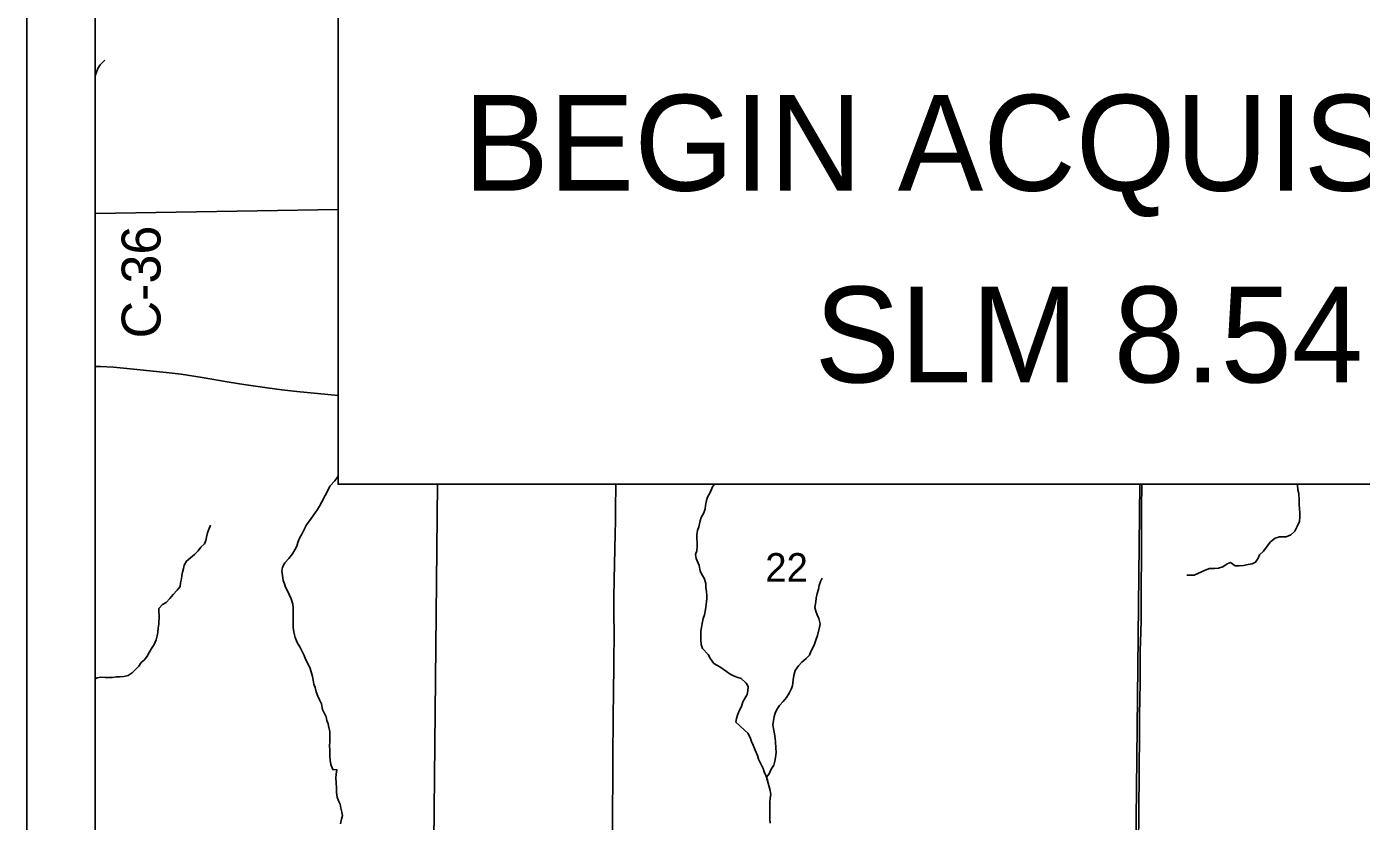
# Model space of a CAD drawing. Extents: x 0 to 34, y 0 to 22.
# Drawn here: x 2 to 3.95, y 18.022 to 19.182 of the extents above; entities that cross this region are included whole.
import ezdxf

# ---------------------------------------------------------------- set-up
doc = ezdxf.new("R2010")
doc.units = 0
for name, color, linetype in [('Default', 7, 'Continuous'), ('GM_X_County_Road', 7, 'Continuous'), ('GM_X_County_Road_Text', 7, 'Continuous'), ('GM_X_Minor_River', 7, 'Continuous'), ('GM_X_Section', 7, 'Continuous'), ('GM_X_Section_Text', 7, 'Continuous'), ('GM_X_State_Route', 7, 'Continuous'), ('GM_X_Township_Road', 7, 'Continuous'), ('SH_Data', 7, 'Continuous'), ('SH_Text', 7, 'Continuous')]:
    doc.layers.add(name, color=color, linetype=linetype)

msp = doc.modelspace()

# ---------------------------------------------------------------- linework, layer by layer
at = {"layer": 'Default'}
for points in [[(2.6062, 19.2311), (2.6102, 19.9231), (2.1, 19.9187), (2.1, 18.9091), (2.4548, 18.9153), (2.4548, 19.2311)], [(2.4548, 18.9153), (2.1, 18.9091), (2.1, 17.8937), (2.5938, 17.8965), (2.6002, 18.514), (2.4548, 18.514)]]:
    msp.add_lwpolyline(points, close=True, dxfattribs=at)
at = {"layer": 'GM_X_County_Road'}
msp.add_lwpolyline([(2.855, 17.896), (2.8551, 17.9234), (2.8554, 17.9703), (2.8559, 18.0107), (2.8562, 18.1102), (2.8563, 18.1288), (2.8567, 18.1597), (2.8569, 18.1752), (2.8573, 18.2095), (2.8578, 18.2498), (2.8579, 18.2683), (2.8581, 18.2828), (2.8581, 18.3026), (2.8579, 18.3181), (2.8579, 18.3492), (2.8581, 18.3742), (2.8598, 18.4422), (2.8601, 18.4603), (2.8603, 18.4764), (2.8608, 18.514)], dxfattribs=at)
at = {"layer": 'GM_X_Minor_River'}
for points in [[(2.1, 19.1106), (2.1018, 19.1159), (2.104, 19.1209), (2.1074, 19.1266), (2.1142, 19.1331)], [(2.4586, 18.0183), (2.4601, 18.0248), (2.4612, 18.0301), (2.4604, 18.0351), (2.4589, 18.0408), (2.4577, 18.0469), (2.4554, 18.0518), (2.4535, 18.0571), (2.4527, 18.0639), (2.4526, 18.07), (2.4522, 18.0784), (2.4518, 18.0849), (2.4522, 18.0906), (2.4529, 18.097), (2.4472, 18.0974), (2.4441, 18.1046), (2.4433, 18.111), (2.4429, 18.1167), (2.4429, 18.1263), (2.4424, 18.132), (2.4428, 18.138), (2.4427, 18.1529), (2.4415, 18.1589), (2.4404, 18.1639), (2.4385, 18.1692), (2.4373, 18.1745), (2.4323, 18.1851), (2.4307, 18.1931), (2.4277, 18.1992), (2.4254, 18.2045), (2.4231, 18.2106), (2.4215, 18.217), (2.4196, 18.222), (2.4184, 18.228), (2.4176, 18.2334), (2.4157, 18.2402), (2.4134, 18.2463), (2.4072, 18.2584), (2.4053, 18.2637), (2.4026, 18.2698), (2.3988, 18.2766), (2.3953, 18.2831), (2.3923, 18.2903), (2.39, 18.2979), (2.3892, 18.3047), (2.3895, 18.3127), (2.3894, 18.3336), (2.3886, 18.3386), (2.3863, 18.3465), (2.3832, 18.353), (2.3809, 18.3583), (2.3782, 18.3636), (2.3767, 18.3685), (2.3748, 18.3735), (2.3736, 18.3807), (2.3728, 18.3868), (2.3739, 18.3929), (2.3773, 18.3993), (2.3829, 18.4054), (2.3882, 18.4123), (2.3916, 18.418), (2.3946, 18.4234), (2.3961, 18.4291), (2.3983, 18.4352), (2.4021, 18.4413), (2.4055, 18.4477), (2.4089, 18.4546), (2.4157, 18.4638), (2.4213, 18.4722), (2.4247, 18.4771), (2.4277, 18.4821), (2.4311, 18.4882), (2.436, 18.4973), (2.4397, 18.5046), (2.4427, 18.511), (2.4503, 18.5191), (2.4533, 18.524), (2.4548, 18.526)], [(3.0861, 18.0668), (3.083, 18.0774), (3.0822, 18.0824), (3.0799, 18.0885), (3.0772, 18.0938), (3.0757, 18.0987), (3.073, 18.1048), (3.0691, 18.1127), (3.0676, 18.1177), (3.0641, 18.1257), (3.0614, 18.1329), (3.0588, 18.1382), (3.0568, 18.1439), (3.0534, 18.1507), (3.0484, 18.1549), (3.0416, 18.1613), (3.0358, 18.1666), (3.037, 18.1719), (3.0388, 18.178), (3.0414, 18.1841), (3.0441, 18.1894), (3.0463, 18.1963), (3.0497, 18.202), (3.0523, 18.207), (3.0534, 18.2123), (3.0538, 18.2184), (3.0511, 18.2237), (3.0439, 18.2301), (3.0374, 18.2324), (3.0324, 18.2342), (3.0275, 18.2365), (3.0222, 18.2407), (3.0126, 18.2471), (3.0039, 18.252), (2.9989, 18.2592), (2.9955, 18.2653), (2.9871, 18.274), (2.9855, 18.2797), (2.9847, 18.2873), (2.9847, 18.2945), (2.985, 18.2994), (2.9858, 18.3048), (2.9869, 18.3108), (2.988, 18.3181), (2.9902, 18.3234), (2.9917, 18.331), (2.9928, 18.3382), (2.9935, 18.347), (2.9935, 18.3519), (2.9931, 18.3569), (2.9923, 18.3633), (2.9919, 18.369), (2.9896, 18.3766), (2.9861, 18.3823), (2.9838, 18.3876), (2.9823, 18.3952), (2.978, 18.4055), (2.9769, 18.4112), (2.9787, 18.4169), (2.9795, 18.4237), (2.9794, 18.4294), (2.979, 18.4344), (2.979, 18.4405), (2.9801, 18.4465), (2.982, 18.4519), (2.9838, 18.4603), (2.9853, 18.4656), (2.9891, 18.4724), (2.9909, 18.4782), (2.9917, 18.4831), (2.9932, 18.49), (2.9943, 18.4949), (2.9984, 18.5021), (3.0018, 18.5101), (3.0047, 18.514)], [(3.8563, 18.514), (3.8564, 18.5133), (3.8568, 18.5057), (3.8584, 18.5004), (3.8588, 18.4909), (3.8588, 18.484), (3.8593, 18.4787), (3.86, 18.4719), (3.8597, 18.4662), (3.8594, 18.4597), (3.856, 18.4525), (3.8526, 18.4456), (3.8466, 18.4402), (3.8397, 18.4372), (3.8299, 18.4371), (3.8238, 18.4352), (3.817, 18.4298), (3.8106, 18.4215), (3.8065, 18.4161), (3.8008, 18.4111), (3.7989, 18.4062), (3.7952, 18.4001), (3.7902, 18.3978), (3.7845, 18.397), (3.7777, 18.3954), (3.7713, 18.395), (3.7652, 18.3946), (3.7587, 18.3999), (3.7538, 18.3976), (3.7474, 18.3934), (3.7409, 18.3915), (3.7352, 18.3911), (3.728, 18.3907), (3.7216, 18.3883), (3.711, 18.3837), (3.7053, 18.381), (3.6996, 18.381), (3.6947, 18.3814)], [(2.1, 18.23), (2.103, 18.2312), (2.1083, 18.232), (2.1144, 18.2316), (2.1254, 18.2317), (2.1307, 18.2325), (2.1356, 18.2329), (2.1421, 18.2333), (2.1481, 18.2348), (2.1542, 18.2386), (2.1591, 18.2432), (2.1636, 18.2482), (2.167, 18.2535), (2.1719, 18.2577), (2.1761, 18.2631), (2.1791, 18.2684), (2.1825, 18.2741), (2.1862, 18.2798), (2.1889, 18.2867), (2.1907, 18.2928), (2.1915, 18.2977), (2.1922, 18.3038), (2.1929, 18.3095), (2.1936, 18.3225), (2.1928, 18.3278), (2.1932, 18.3327), (2.1985, 18.3385), (2.2038, 18.3415), (2.209, 18.3469), (2.2139, 18.353), (2.22, 18.3591), (2.2241, 18.3648), (2.2249, 18.3701), (2.226, 18.3758), (2.2267, 18.3808), (2.2278, 18.3857), (2.2289, 18.3911), (2.23, 18.396), (2.2334, 18.4017), (2.2391, 18.4063), (2.2451, 18.4113), (2.2504, 18.4166), (2.2546, 18.422), (2.2599, 18.4269), (2.2617, 18.4319), (2.2628, 18.4368), (2.2643, 18.4429), (2.2666, 18.4494), (2.2684, 18.4544)], [(3.0861, 18.0668), (3.0807, 18.0862), (3.0848, 18.0911), (3.0874, 18.098), (3.0916, 18.1037), (3.0931, 18.1098), (3.0938, 18.1148), (3.0949, 18.1224), (3.0945, 18.1292), (3.0937, 18.1376), (3.0933, 18.1429), (3.0925, 18.1497), (3.0909, 18.1569), (3.0901, 18.163), (3.0909, 18.1684), (3.092, 18.1748), (3.0935, 18.1798), (3.0957, 18.1851), (3.0995, 18.1908), (3.1048, 18.1966), (3.1097, 18.2027), (3.1138, 18.2088), (3.1168, 18.2145), (3.1187, 18.2198), (3.1198, 18.2282), (3.1205, 18.2346), (3.1224, 18.2419), (3.1273, 18.2487), (3.1325, 18.2541), (3.1386, 18.2594), (3.1435, 18.2644), (3.1457, 18.2697), (3.1484, 18.2751), (3.1506, 18.2804), (3.1532, 18.2876), (3.1551, 18.293), (3.1581, 18.3052), (3.1592, 18.3101), (3.1572, 18.3181), (3.1546, 18.3234), (3.1526, 18.3287), (3.1515, 18.334), (3.1529, 18.3424), (3.1533, 18.3477), (3.1548, 18.3546), (3.1566, 18.3607), (3.1578, 18.366), (3.1596, 18.3717), (3.1619, 18.3767)], [(3.086, 18.0189), (3.0855, 18.0246), (3.0855, 18.0364), (3.0858, 18.0421), (3.0858, 18.0497), (3.0861, 18.0554), (3.0869, 18.0607), (3.0861, 18.0668)]]:
    msp.add_lwpolyline(points, dxfattribs=at)
at = {"layer": 'GM_X_Section'}
for points in [[(2.6002, 18.514), (2.5938, 17.8965), (3.6191, 17.892), (3.6261, 18.514)], [(3.6261, 18.514), (3.6191, 17.892), (4.6321, 17.8882), (4.6433, 18.514)]]:
    msp.add_lwpolyline(points, close=True, dxfattribs=at)
at = {"layer": 'GM_X_State_Route'}
for points in [[(5.6507, 20.9), (2.1, 20.9), (2.1, 15.8695)], [(2.1, 18.6861), (2.108, 18.686), (2.1267, 18.6848), (2.1607, 18.6817), (2.2039, 18.6773), (2.2255, 18.6746), (2.2562, 18.6698), (2.2959, 18.6628), (2.3174, 18.6594), (2.3512, 18.6546), (2.3728, 18.6519), (2.3944, 18.6496), (2.4548, 18.6434)]]:
    msp.add_lwpolyline(points, dxfattribs=at)
at = {"layer": 'GM_X_Township_Road'}
msp.add_lwpolyline([(3.6233, 17.8916), (3.6237, 17.9253), (3.624, 17.9843), (3.6246, 18.0372), (3.625, 18.093), (3.6255, 18.152), (3.6257, 18.1769), (3.6263, 18.2235), (3.6267, 18.2545), (3.6267, 18.27), (3.6271, 18.2854), (3.6275, 18.2977), (3.6278, 18.3163), (3.6278, 18.3629), (3.6284, 18.4095), (3.6287, 18.4406), (3.6287, 18.4779), (3.6292, 18.514)], dxfattribs=at)
at = {"layer": 'SH_Data'}
for p, q in [((2, 21), (2, 14)), ((2.1, 20.9), (2.1, 14.1))]:
    msp.add_line(p, q, dxfattribs=at)
at = {"layer": 'SH_Text'}
msp.add_lwpolyline([(2.4548, 19.2311), (4.6746, 19.2311), (4.6746, 18.514), (2.4548, 18.514)], close=True, dxfattribs=at)

# ---------------------------------------------------------------- texts
at = {"layer": 'GM_X_County_Road_Text'}
msp.add_text('C-36', height=0.05682, rotation=90, dxfattribs=at).set_placement((2.1955, 18.7269))
at = {"layer": 'GM_X_Section_Text'}
msp.add_text('22', height=0.04186, rotation=0, dxfattribs=at).set_placement((3.0789, 18.3715))
at = {"layer": 'SH_Text'}
for s, p in [('BEGIN ACQUISTION', (2.6379, 18.9426)), ('SLM 8.54', (3.1509, 18.6626))]:
    msp.add_text(s, height=0.14, dxfattribs=at).set_placement(p)

doc.saveas('drawing.dxf')
